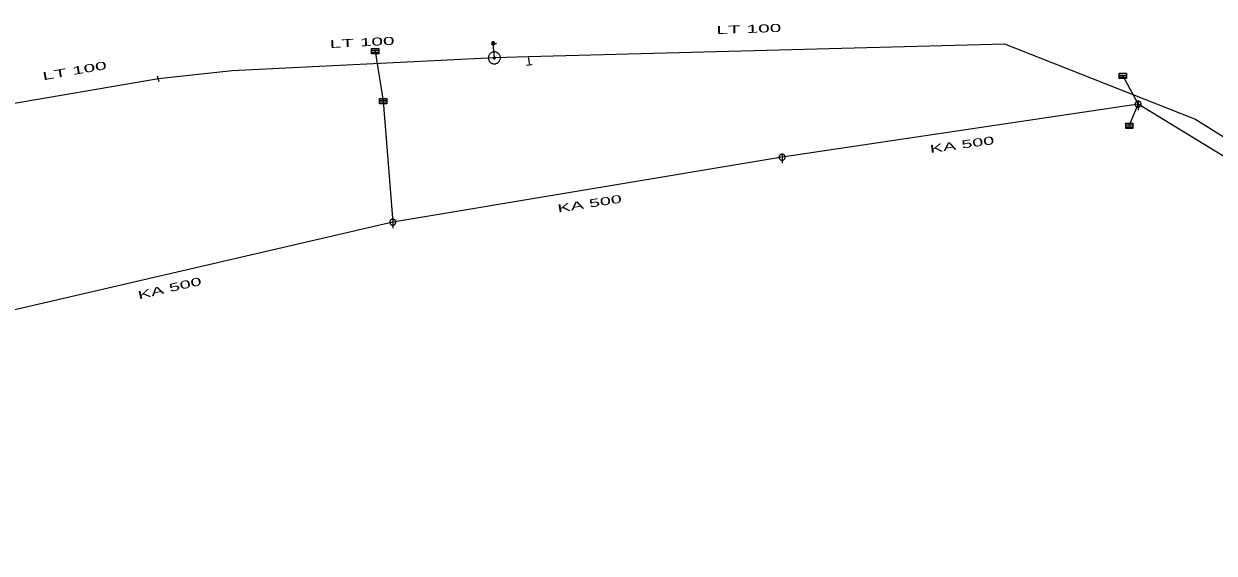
# Model space of a CAD drawing. Extents: x -687468 to -685917, y -974192 to -973456.
# Drawn here: x -686735.6 to -686636.4, y -973717.7 to -973673.6 of the extents above; entities that cross this region are included whole.
import ezdxf
from ezdxf.enums import TextEntityAlignment as Align

# ---------------------------------------------------------------- set-up
doc = ezdxf.new("R2010")
doc.units = 0
doc.header["$LTSCALE"] = 0.27
for name, color, linetype, lineweight in [('1', 7, 'Continuous', 13), ('11', 7, 'Continuous', 13), ('14', 7, 'Continuous', 25), ('17', 7, 'Continuous', 25), ('22', 7, 'Continuous', 13), ('34', 7, 'Continuous', 13), ('47', 7, 'Continuous', 13), ('9', 7, 'Continuous', 13)]:
    doc.layers.add(name, color=color, linetype=linetype, lineweight=lineweight)

msp = doc.modelspace()

# ---------------------------------------------------------------- linework, layer by layer
at = {"layer": '11'}
for p in [(-686643.98, -973677.98), (-686643.45, -973682.14)]:
    msp.add_line(p, (-686642.71, -973680.34), dxfattribs=at)
msp.add_lwpolyline([(-686706.28, -973675.92), (-686705.62, -973680.08), (-686704.81, -973690.17)], dxfattribs=at)
at = {"layer": '14', "lineweight": 13}
for p, q in [((-686696.345, -973676.48), (-686696.449, -973675.269)), ((-686693.532, -973676.405), (-686693.429, -973677.059))]:
    msp.add_line(p, q, dxfattribs=at)
at = {"layer": '14'}
for p, q in [((-686642.71, -973680.34), (-686672.372, -973684.756)), ((-686617.8, -973695.539), (-686642.71, -973680.34)), ((-686672.372, -973684.756), (-686704.809, -973690.17)), ((-686704.809, -973690.17), (-686742.511, -973698.919))]:
    msp.add_line(p, q, dxfattribs=at)
at = {"layer": '17'}
msp.add_line((-686724.343, -973678.231), (-686737.661, -973680.49), dxfattribs=at)
for points in [[(-686506.346, -973717.746), (-686529.344, -973710.524), (-686536.247, -973707.872), (-686555.026, -973699.577), (-686572.978, -973698.129), (-686583.112, -973698.418), (-686615.962, -973695.359), (-686637.993, -973681.581), (-686653.818, -973675.34), (-686693.532, -973676.405), (-686696.345, -973676.48)], [(-686696.345, -973676.48), (-686718.181, -973677.546), (-686724.343, -973678.231)]]:
    msp.add_lwpolyline(points, dxfattribs=at)
at = {"layer": '22'}
for p, q in [((-686706.575, -973675.849), (-686705.977, -973675.849)), ((-686706.575, -973675.995), (-686705.977, -973675.995)), ((-686644.275, -973677.909), (-686643.677, -973677.909)), ((-686644.275, -973678.054), (-686643.677, -973678.054)), ((-686705.915, -973680.009), (-686705.317, -973680.009)), ((-686705.915, -973680.154), (-686705.317, -973680.154)), ((-686642.709, -973680.088), (-686642.71, -973680.831)), ((-686643.745, -973682.069), (-686643.147, -973682.069)), ((-686643.745, -973682.215), (-686643.147, -973682.215)), ((-686672.371, -973684.505), (-686672.372, -973685.249)), ((-686704.809, -973689.918), (-686704.81, -973690.662))]:
    msp.add_line(p, q, dxfattribs=at)
for points in [[(-686706.575, -973675.703), (-686705.977, -973675.703), (-686705.977, -973676.14), (-686706.575, -973676.14)], [(-686644.275, -973677.763), (-686643.677, -973677.763), (-686643.677, -973678.2), (-686644.275, -973678.2)], [(-686705.915, -973679.863), (-686705.317, -973679.863), (-686705.317, -973680.299), (-686705.915, -973680.299)], [(-686642.458, -973680.34), (-686642.459, -973680.314), (-686642.463, -973680.288), (-686642.469, -973680.262), (-686642.479, -973680.238), (-686642.491, -973680.214), (-686642.505, -973680.192), (-686642.522, -973680.171), (-686642.54, -973680.153), (-686642.561, -973680.136), (-686642.583, -973680.122), (-686642.607, -973680.11), (-686642.631, -973680.1), (-686642.657, -973680.094), (-686642.683, -973680.09), (-686642.709, -973680.088), (-686642.735, -973680.089), (-686642.761, -973680.093), (-686642.787, -973680.099), (-686642.812, -973680.109), (-686642.835, -973680.121), (-686642.857, -973680.135), (-686642.878, -973680.152), (-686642.896, -973680.17), (-686642.913, -973680.191), (-686642.927, -973680.213), (-686642.939, -973680.237), (-686642.949, -973680.261), (-686642.956, -973680.287), (-686642.96, -973680.313), (-686642.962, -973680.339), (-686642.961, -973680.365), (-686642.957, -973680.391), (-686642.95, -973680.417), (-686642.94, -973680.442), (-686642.928, -973680.465), (-686642.914, -973680.487), (-686642.897, -973680.508), (-686642.879, -973680.526), (-686642.858, -973680.543), (-686642.836, -973680.557), (-686642.813, -973680.569), (-686642.788, -973680.579), (-686642.762, -973680.586), (-686642.736, -973680.59), (-686642.71, -973680.592), (-686642.684, -973680.591), (-686642.658, -973680.587), (-686642.632, -973680.58), (-686642.608, -973680.57), (-686642.584, -973680.558), (-686642.562, -973680.544), (-686642.541, -973680.527), (-686642.523, -973680.509), (-686642.506, -973680.488), (-686642.492, -973680.466), (-686642.48, -973680.443), (-686642.47, -973680.418), (-686642.464, -973680.392), (-686642.46, -973680.366)], [(-686643.745, -973681.923), (-686643.147, -973681.923), (-686643.147, -973682.36), (-686643.745, -973682.36)], [(-686672.12, -973684.757), (-686672.121, -973684.731), (-686672.125, -973684.705), (-686672.131, -973684.679), (-686672.141, -973684.655), (-686672.153, -973684.631), (-686672.167, -973684.609), (-686672.184, -973684.588), (-686672.202, -973684.57), (-686672.223, -973684.553), (-686672.245, -973684.539), (-686672.269, -973684.527), (-686672.293, -973684.517), (-686672.319, -973684.511), (-686672.345, -973684.507), (-686672.371, -973684.505), (-686672.397, -973684.506), (-686672.423, -973684.51), (-686672.449, -973684.516), (-686672.474, -973684.526), (-686672.497, -973684.538), (-686672.519, -973684.552), (-686672.54, -973684.569), (-686672.558, -973684.587), (-686672.575, -973684.608), (-686672.589, -973684.63), (-686672.601, -973684.654), (-686672.611, -973684.678), (-686672.618, -973684.704), (-686672.622, -973684.73), (-686672.624, -973684.756), (-686672.623, -973684.782), (-686672.619, -973684.808), (-686672.612, -973684.834), (-686672.602, -973684.859), (-686672.59, -973684.882), (-686672.576, -973684.904), (-686672.559, -973684.925), (-686672.541, -973684.943), (-686672.52, -973684.96), (-686672.498, -973684.974), (-686672.475, -973684.986), (-686672.45, -973684.996), (-686672.424, -973685.003), (-686672.398, -973685.007), (-686672.372, -973685.009), (-686672.346, -973685.008), (-686672.32, -973685.004), (-686672.294, -973684.997), (-686672.27, -973684.987), (-686672.246, -973684.975), (-686672.224, -973684.961), (-686672.203, -973684.944), (-686672.185, -973684.926), (-686672.168, -973684.905), (-686672.154, -973684.883), (-686672.142, -973684.86), (-686672.132, -973684.835), (-686672.126, -973684.809), (-686672.122, -973684.783)], [(-686704.558, -973690.17), (-686704.559, -973690.144), (-686704.563, -973690.118), (-686704.569, -973690.092), (-686704.579, -973690.068), (-686704.591, -973690.044), (-686704.605, -973690.022), (-686704.622, -973690.001), (-686704.64, -973689.983), (-686704.661, -973689.966), (-686704.683, -973689.952), (-686704.707, -973689.94), (-686704.731, -973689.93), (-686704.757, -973689.924), (-686704.783, -973689.92), (-686704.809, -973689.918), (-686704.835, -973689.919), (-686704.861, -973689.923), (-686704.887, -973689.929), (-686704.912, -973689.939), (-686704.935, -973689.951), (-686704.957, -973689.965), (-686704.978, -973689.982), (-686704.996, -973690), (-686705.013, -973690.021), (-686705.027, -973690.043), (-686705.039, -973690.067), (-686705.049, -973690.091), (-686705.056, -973690.117), (-686705.06, -973690.143), (-686705.062, -973690.169), (-686705.061, -973690.195), (-686705.057, -973690.221), (-686705.05, -973690.247), (-686705.04, -973690.272), (-686705.028, -973690.295), (-686705.014, -973690.317), (-686704.997, -973690.338), (-686704.979, -973690.356), (-686704.958, -973690.373), (-686704.936, -973690.387), (-686704.913, -973690.399), (-686704.888, -973690.409), (-686704.862, -973690.416), (-686704.836, -973690.42), (-686704.81, -973690.422), (-686704.784, -973690.421), (-686704.758, -973690.417), (-686704.732, -973690.41), (-686704.708, -973690.4), (-686704.684, -973690.388), (-686704.662, -973690.374), (-686704.641, -973690.357), (-686704.623, -973690.339), (-686704.606, -973690.318), (-686704.592, -973690.296), (-686704.58, -973690.273), (-686704.57, -973690.248), (-686704.564, -973690.222), (-686704.56, -973690.196)]]:
    msp.add_lwpolyline(points, close=True, dxfattribs=at)
at = {"layer": '34'}
for p, q in [((-686693.674, -973677.097), (-686693.183, -973677.02)), ((-686724.27, -973678.468), (-686724.415, -973677.993))]:
    msp.add_line(p, q, dxfattribs=at)
at = {"layer": '47'}
for points in [[(-686695.885, -973676.676), (-686695.867, -973676.627), (-686695.854, -973676.576), (-686695.847, -973676.524), (-686695.844, -973676.472), (-686695.848, -973676.42), (-686695.858, -973676.368), (-686695.872, -973676.318), (-686695.892, -973676.269), (-686695.915, -973676.223), (-686695.945, -973676.179), (-686695.978, -973676.139), (-686696.016, -973676.103), (-686696.057, -973676.071), (-686696.102, -973676.043), (-686696.148, -973676.02), (-686696.197, -973676.002), (-686696.248, -973675.989), (-686696.301, -973675.982), (-686696.352, -973675.979), (-686696.404, -973675.983), (-686696.456, -973675.993), (-686696.507, -973676.007), (-686696.555, -973676.026), (-686696.602, -973676.05), (-686696.645, -973676.08), (-686696.685, -973676.113), (-686696.722, -973676.151), (-686696.753, -973676.192), (-686696.781, -973676.237), (-686696.804, -973676.283), (-686696.822, -973676.332), (-686696.835, -973676.383), (-686696.843, -973676.435), (-686696.845, -973676.487), (-686696.841, -973676.539), (-686696.832, -973676.591), (-686696.818, -973676.642), (-686696.799, -973676.69), (-686696.774, -973676.737), (-686696.744, -973676.78), (-686696.711, -973676.82), (-686696.674, -973676.856), (-686696.632, -973676.888), (-686696.587, -973676.916), (-686696.541, -973676.939), (-686696.492, -973676.957), (-686696.441, -973676.97), (-686696.39, -973676.978), (-686696.337, -973676.98), (-686696.285, -973676.976), (-686696.233, -973676.967), (-686696.183, -973676.953), (-686696.135, -973676.933), (-686696.088, -973676.909), (-686696.044, -973676.879), (-686696.004, -973676.846), (-686695.969, -973676.809), (-686695.936, -973676.767), (-686695.908, -973676.722)], [(-686696.269, -973676.512), (-686696.266, -973676.503), (-686696.264, -973676.495), (-686696.263, -973676.487), (-686696.263, -973676.479), (-686696.263, -973676.47), (-686696.265, -973676.461), (-686696.267, -973676.453), (-686696.27, -973676.445), (-686696.274, -973676.438), (-686696.279, -973676.43), (-686696.285, -973676.423), (-686696.291, -973676.418), (-686696.297, -973676.413), (-686696.304, -973676.408), (-686696.312, -973676.404), (-686696.321, -973676.401), (-686696.329, -973676.399), (-686696.337, -973676.398), (-686696.345, -973676.398), (-686696.354, -973676.398), (-686696.363, -973676.4), (-686696.371, -973676.402), (-686696.379, -973676.405), (-686696.387, -973676.409), (-686696.394, -973676.414), (-686696.401, -973676.42), (-686696.406, -973676.426), (-686696.411, -973676.432), (-686696.416, -973676.439), (-686696.42, -973676.447), (-686696.423, -973676.456), (-686696.425, -973676.464), (-686696.426, -973676.472), (-686696.426, -973676.48), (-686696.426, -973676.489), (-686696.425, -973676.497), (-686696.422, -973676.506), (-686696.419, -973676.514), (-686696.415, -973676.522), (-686696.41, -973676.529), (-686696.404, -973676.536), (-686696.398, -973676.541), (-686696.392, -973676.546), (-686696.385, -973676.551), (-686696.377, -973676.555), (-686696.368, -973676.558), (-686696.36, -973676.56), (-686696.352, -973676.561), (-686696.344, -973676.561), (-686696.335, -973676.561), (-686696.327, -973676.56), (-686696.318, -973676.557), (-686696.31, -973676.554), (-686696.303, -973676.55), (-686696.295, -973676.545), (-686696.288, -973676.539), (-686696.283, -973676.533), (-686696.278, -973676.527), (-686696.273, -973676.52)]]:
    msp.add_lwpolyline(points, close=True, dxfattribs=at)
at = {"layer": '9'}
msp.add_line((-686696.323, -973675.269), (-686696.197, -973675.269), dxfattribs=at)
for points in [[(-686696.449, -973675.395), (-686696.436, -973675.394), (-686696.423, -973675.392), (-686696.41, -973675.389), (-686696.398, -973675.384), (-686696.386, -973675.378), (-686696.375, -973675.371), (-686696.365, -973675.363), (-686696.355, -973675.353), (-686696.347, -973675.343), (-686696.34, -973675.332), (-686696.334, -973675.32), (-686696.329, -973675.308), (-686696.326, -973675.295), (-686696.324, -973675.282), (-686696.323, -973675.269), (-686696.323, -973675.256), (-686696.325, -973675.243), (-686696.328, -973675.23), (-686696.333, -973675.218), (-686696.339, -973675.206), (-686696.346, -973675.195), (-686696.354, -973675.185), (-686696.364, -973675.175), (-686696.374, -973675.167), (-686696.385, -973675.16), (-686696.397, -973675.154), (-686696.409, -973675.149), (-686696.422, -973675.146), (-686696.435, -973675.144), (-686696.448, -973675.142), (-686696.461, -973675.143), (-686696.474, -973675.145), (-686696.487, -973675.148), (-686696.499, -973675.153), (-686696.511, -973675.159), (-686696.522, -973675.166), (-686696.532, -973675.174), (-686696.542, -973675.184), (-686696.55, -973675.194), (-686696.557, -973675.205), (-686696.563, -973675.217), (-686696.568, -973675.229), (-686696.571, -973675.242), (-686696.573, -973675.255), (-686696.575, -973675.268), (-686696.574, -973675.281), (-686696.572, -973675.294), (-686696.569, -973675.307), (-686696.564, -973675.319), (-686696.558, -973675.331), (-686696.551, -973675.342), (-686696.543, -973675.352), (-686696.533, -973675.362), (-686696.523, -973675.37), (-686696.512, -973675.377), (-686696.5, -973675.383), (-686696.488, -973675.388), (-686696.475, -973675.391), (-686696.462, -973675.393)], [(-686696.449, -973675.375), (-686696.438, -973675.375), (-686696.427, -973675.373), (-686696.416, -973675.37), (-686696.406, -973675.366), (-686696.396, -973675.361), (-686696.387, -973675.355), (-686696.378, -973675.348), (-686696.37, -973675.34), (-686696.363, -973675.331), (-686696.357, -973675.322), (-686696.352, -973675.312), (-686696.348, -973675.302), (-686696.345, -973675.291), (-686696.343, -973675.28), (-686696.343, -973675.269), (-686696.342, -973675.258), (-686696.344, -973675.247), (-686696.347, -973675.236), (-686696.351, -973675.226), (-686696.356, -973675.216), (-686696.362, -973675.207), (-686696.369, -973675.198), (-686696.377, -973675.19), (-686696.386, -973675.183), (-686696.395, -973675.177), (-686696.405, -973675.172), (-686696.415, -973675.168), (-686696.426, -973675.165), (-686696.437, -973675.163), (-686696.448, -973675.163), (-686696.459, -973675.162), (-686696.47, -973675.164), (-686696.481, -973675.167), (-686696.491, -973675.171), (-686696.501, -973675.176), (-686696.51, -973675.182), (-686696.519, -973675.189), (-686696.527, -973675.197), (-686696.534, -973675.206), (-686696.54, -973675.215), (-686696.545, -973675.225), (-686696.549, -973675.235), (-686696.552, -973675.246), (-686696.554, -973675.257), (-686696.555, -973675.268), (-686696.555, -973675.279), (-686696.553, -973675.29), (-686696.55, -973675.301), (-686696.546, -973675.311), (-686696.541, -973675.321), (-686696.535, -973675.33), (-686696.528, -973675.339), (-686696.52, -973675.347), (-686696.511, -973675.354), (-686696.502, -973675.36), (-686696.492, -973675.365), (-686696.482, -973675.369), (-686696.471, -973675.372), (-686696.46, -973675.374)], [(-686696.449, -973675.356), (-686696.44, -973675.355), (-686696.431, -973675.354), (-686696.422, -973675.351), (-686696.414, -973675.348), (-686696.406, -973675.344), (-686696.398, -973675.339), (-686696.391, -973675.333), (-686696.385, -973675.327), (-686696.379, -973675.32), (-686696.374, -973675.312), (-686696.37, -973675.304), (-686696.367, -973675.296), (-686696.364, -973675.287), (-686696.363, -973675.278), (-686696.362, -973675.269), (-686696.362, -973675.26), (-686696.363, -973675.251), (-686696.366, -973675.242), (-686696.369, -973675.234), (-686696.373, -973675.226), (-686696.378, -973675.218), (-686696.384, -973675.211), (-686696.39, -973675.205), (-686696.397, -973675.199), (-686696.405, -973675.194), (-686696.413, -973675.19), (-686696.421, -973675.187), (-686696.43, -973675.184), (-686696.439, -973675.183), (-686696.448, -973675.181), (-686696.457, -973675.182), (-686696.466, -973675.183), (-686696.475, -973675.186), (-686696.483, -973675.189), (-686696.491, -973675.193), (-686696.499, -973675.198), (-686696.506, -973675.204), (-686696.512, -973675.21), (-686696.518, -973675.217), (-686696.523, -973675.225), (-686696.527, -973675.233), (-686696.53, -973675.241), (-686696.533, -973675.25), (-686696.534, -973675.259), (-686696.536, -973675.268), (-686696.535, -973675.277), (-686696.534, -973675.286), (-686696.531, -973675.295), (-686696.528, -973675.303), (-686696.524, -973675.311), (-686696.519, -973675.319), (-686696.513, -973675.326), (-686696.507, -973675.332), (-686696.5, -973675.338), (-686696.492, -973675.343), (-686696.484, -973675.347), (-686696.476, -973675.35), (-686696.467, -973675.353), (-686696.458, -973675.354)], [(-686696.449, -973675.336), (-686696.442, -973675.336), (-686696.435, -973675.334), (-686696.428, -973675.333), (-686696.422, -973675.33), (-686696.416, -973675.327), (-686696.41, -973675.323), (-686696.404, -973675.319), (-686696.399, -973675.314), (-686696.395, -973675.308), (-686696.391, -973675.302), (-686696.388, -973675.296), (-686696.385, -973675.29), (-686696.384, -973675.283), (-686696.382, -973675.276), (-686696.382, -973675.269), (-686696.381, -973675.262), (-686696.383, -973675.255), (-686696.384, -973675.248), (-686696.387, -973675.242), (-686696.39, -973675.235), (-686696.394, -973675.23), (-686696.398, -973675.224), (-686696.403, -973675.219), (-686696.409, -973675.215), (-686696.415, -973675.211), (-686696.421, -973675.208), (-686696.427, -973675.205), (-686696.434, -973675.203), (-686696.441, -973675.202), (-686696.448, -973675.201), (-686696.455, -973675.201), (-686696.462, -973675.202), (-686696.469, -973675.204), (-686696.475, -973675.207), (-686696.482, -973675.21), (-686696.487, -973675.214), (-686696.493, -973675.218), (-686696.498, -973675.223), (-686696.502, -973675.229), (-686696.506, -973675.234), (-686696.509, -973675.241), (-686696.512, -973675.247), (-686696.514, -973675.254), (-686696.515, -973675.261), (-686696.516, -973675.268), (-686696.516, -973675.275), (-686696.515, -973675.282), (-686696.513, -973675.289), (-686696.51, -973675.295), (-686696.507, -973675.301), (-686696.503, -973675.307), (-686696.499, -973675.313), (-686696.494, -973675.318), (-686696.488, -973675.322), (-686696.483, -973675.326), (-686696.476, -973675.329), (-686696.47, -973675.332), (-686696.463, -973675.333), (-686696.456, -973675.335)], [(-686696.449, -973675.316), (-686696.444, -973675.316), (-686696.439, -973675.315), (-686696.434, -973675.314), (-686696.43, -973675.312), (-686696.425, -973675.31), (-686696.421, -973675.307), (-686696.418, -973675.304), (-686696.414, -973675.3), (-686696.411, -973675.297), (-686696.408, -973675.293), (-686696.406, -973675.288), (-686696.404, -973675.284), (-686696.403, -973675.279), (-686696.402, -973675.274), (-686696.402, -973675.269), (-686696.401, -973675.264), (-686696.402, -973675.259), (-686696.403, -973675.254), (-686696.405, -973675.25), (-686696.407, -973675.245), (-686696.41, -973675.241), (-686696.413, -973675.237), (-686696.417, -973675.234), (-686696.42, -973675.231), (-686696.424, -973675.228), (-686696.429, -973675.226), (-686696.433, -973675.224), (-686696.438, -973675.223), (-686696.443, -973675.222), (-686696.448, -973675.222), (-686696.453, -973675.221), (-686696.458, -973675.222), (-686696.463, -973675.223), (-686696.467, -973675.225), (-686696.472, -973675.227), (-686696.476, -973675.23), (-686696.48, -973675.233), (-686696.483, -973675.236), (-686696.486, -973675.24), (-686696.489, -973675.244), (-686696.491, -973675.249), (-686696.493, -973675.253), (-686696.494, -973675.258), (-686696.495, -973675.263), (-686696.496, -973675.268), (-686696.496, -973675.273), (-686696.495, -973675.278), (-686696.494, -973675.283), (-686696.492, -973675.287), (-686696.49, -973675.292), (-686696.487, -973675.296), (-686696.484, -973675.299), (-686696.481, -973675.303), (-686696.477, -973675.306), (-686696.473, -973675.309), (-686696.468, -973675.311), (-686696.464, -973675.313), (-686696.459, -973675.314), (-686696.454, -973675.315)], [(-686696.449, -973675.296), (-686696.446, -973675.296), (-686696.443, -973675.296), (-686696.441, -973675.295), (-686696.438, -973675.294), (-686696.435, -973675.293), (-686696.433, -973675.291), (-686696.431, -973675.289), (-686696.429, -973675.287), (-686696.427, -973675.285), (-686696.425, -973675.283), (-686696.424, -973675.28), (-686696.423, -973675.277), (-686696.422, -973675.275), (-686696.422, -973675.272), (-686696.422, -973675.269), (-686696.421, -973675.266), (-686696.421, -973675.263), (-686696.422, -973675.26), (-686696.423, -973675.258), (-686696.424, -973675.255), (-686696.426, -973675.253), (-686696.428, -973675.25), (-686696.43, -973675.248), (-686696.432, -973675.247), (-686696.434, -973675.245), (-686696.437, -973675.244), (-686696.44, -973675.243), (-686696.442, -973675.242), (-686696.445, -973675.242), (-686696.448, -973675.24), (-686696.451, -973675.241), (-686696.454, -973675.241), (-686696.457, -973675.242), (-686696.459, -973675.243), (-686696.462, -973675.244), (-686696.464, -973675.246), (-686696.467, -973675.247), (-686696.469, -973675.249), (-686696.47, -973675.252), (-686696.472, -973675.254), (-686696.473, -973675.257), (-686696.474, -973675.259), (-686696.475, -973675.262), (-686696.475, -973675.265), (-686696.477, -973675.268), (-686696.476, -973675.271), (-686696.476, -973675.274), (-686696.475, -973675.276), (-686696.474, -973675.279), (-686696.473, -973675.282), (-686696.471, -973675.284), (-686696.47, -973675.286), (-686696.468, -973675.288), (-686696.465, -973675.29), (-686696.463, -973675.292), (-686696.46, -973675.293), (-686696.458, -973675.294), (-686696.455, -973675.295), (-686696.452, -973675.295)], [(-686696.449, -973675.277), (-686696.448, -973675.277), (-686696.447, -973675.277), (-686696.447, -973675.276), (-686696.446, -973675.276), (-686696.445, -973675.276), (-686696.444, -973675.275), (-686696.444, -973675.275), (-686696.443, -973675.274), (-686696.443, -973675.274), (-686696.442, -973675.273), (-686696.442, -973675.272), (-686696.442, -973675.271), (-686696.441, -973675.271), (-686696.441, -973675.27), (-686696.441, -973675.269), (-686696.441, -973675.268), (-686696.441, -973675.267), (-686696.441, -973675.267), (-686696.441, -973675.266), (-686696.441, -973675.265), (-686696.442, -973675.264), (-686696.442, -973675.264), (-686696.443, -973675.263), (-686696.443, -973675.263), (-686696.444, -973675.262), (-686696.445, -973675.262), (-686696.446, -973675.261), (-686696.446, -973675.261), (-686696.447, -973675.261), (-686696.448, -973675.261), (-686696.449, -973675.261), (-686696.45, -973675.261), (-686696.45, -973675.261), (-686696.451, -973675.261), (-686696.452, -973675.261), (-686696.453, -973675.262), (-686696.453, -973675.262), (-686696.454, -973675.263), (-686696.454, -973675.263), (-686696.455, -973675.264), (-686696.455, -973675.265), (-686696.456, -973675.266), (-686696.456, -973675.266), (-686696.456, -973675.267), (-686696.457, -973675.268), (-686696.457, -973675.269), (-686696.457, -973675.27), (-686696.457, -973675.27), (-686696.456, -973675.271), (-686696.456, -973675.272), (-686696.455, -973675.273), (-686696.455, -973675.273), (-686696.454, -973675.274), (-686696.454, -973675.274), (-686696.453, -973675.275), (-686696.452, -973675.275), (-686696.451, -973675.275), (-686696.451, -973675.276), (-686696.45, -973675.276)]]:
    msp.add_lwpolyline(points, close=True, dxfattribs=at)
msp.add_lwpolyline([(-686696.231, -973675.238), (-686696.197, -973675.269), (-686696.232, -973675.3)], dxfattribs=at)

# ---------------------------------------------------------------- texts
at = {"layer": '1'}
for s, rotation, width, p in [('LT 100', 2, 1.95, (-686675.132, -973674.403)), ('LT 100', 3, 1.95, (-686707.348, -973675.519)), ('LT 100', 10, 1.95, (-686731.27, -973677.875)), ('KA 500', 8, 1.85, (-686657.338, -973684.036)), ('KA 500', 9, 1.85, (-686688.36, -973688.947)), ('KA 500', 13, 1.85, (-686723.328, -973695.987))]:
    msp.add_text(s, height=0.6667, rotation=rotation, dxfattribs=dict(at, width=width)).set_placement(p, align=Align.CENTER)

doc.saveas('drawing.dxf')
